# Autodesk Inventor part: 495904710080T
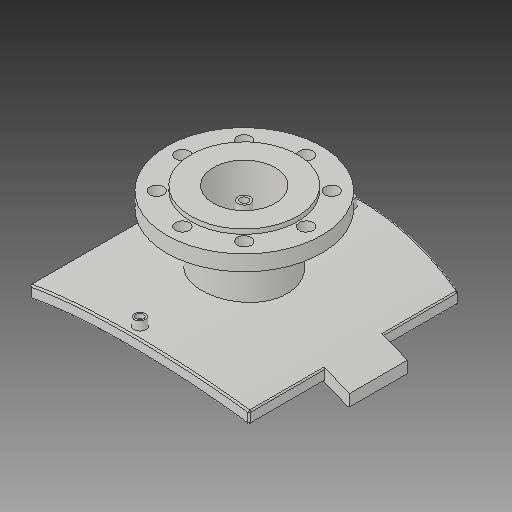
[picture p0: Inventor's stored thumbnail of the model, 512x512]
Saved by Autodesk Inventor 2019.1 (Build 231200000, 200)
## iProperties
Created: 2017-10
Part Number: 495904710080T
Material: Generic
Description: PLASSON FLANGED BRANCH SADDLE 450-800X80
Document SubType Name: Modeling
Designer: KIM
Mass: 2339.99 g
Surface Area: 3251.55 cm^2
Volume: 2339.99 cm^3
Density: 1 g/cm^3
Appearance: Default
Author: KIM
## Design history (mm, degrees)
derived "495904_495903.ipt"
feature "Solid1::495904_495903.ipt"
feature "Solid2::495904_495903.ipt"
tag "TaggingFeature1"
body "Solid1"
other parameters: "d1" = 15, "d2" = 283.5, "d4" = 0, "d6" = 75, "d7" = 0, "d12" = 425.6, "d13" = 14, "d14" = 135, "d16" = 5 deg, "d18" = 4, "d19" = 14, "d20" = 0, "d21" = 3, "d22" = 0, "d36" = 135, "d38" = 0, "d39" = 2, "d42" = 138, "d44" = 84, "d46" = 110.4, "d47" = 16, "d48" = 10.4, "d49" = 73.5, "d51" = 816, "d53" = 0, "d54" = 18, "d57" = 0, "d59" = 360 deg, "d63" = 0, "d66" = 105, "d67" = 15, "d68" = 52.5, "d70" = 0, "d71" = 2, "d72" = 315, "d_1" = 138, "B_" = 315, "H_" = 105, "x_" = 15, "D_" = 16, "s_" = 18
